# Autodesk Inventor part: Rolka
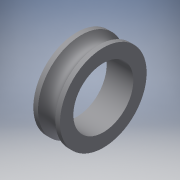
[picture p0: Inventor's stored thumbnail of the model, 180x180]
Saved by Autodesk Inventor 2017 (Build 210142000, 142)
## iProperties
Created: 2021-01
Part Number: Rolka
Material: Ogólny
Document SubType Name: Modeling
Designer: HP
Density: 1 g/cm^3
Appearance: Domyślna
Author: HP
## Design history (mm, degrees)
sketch "Szkic1"
  geometry: L1 (0, 0)-(47.708, 0); L2 (4.065, 4.5)-(0.065, 4.5); L3 (0.065, 4.5)-(0.065, 6.5); L4 (4.065, 4.5)-(4.065, 6.5); L5 (0.065, 6.5)-(0.765, 6.5); L6 (4.065, 6.5)-(3.365, 6.5); L7 (0.765, 6.5)-(2.065, 4.5); L8 (2.065, 4.5)-(3.365, 6.5)
  constraints: 12 end point, 3 horizontal, 1 midpoint, 1 vertical, 3 other
  dimensions: "d0" = 9 diameter of L2 L1; "d15" = 2 distance of L2.end L3.end; "d16" = 2 distance from line of L2 L4.end; "d17" = 4 distance of L4.end L3.end; "d18" = 0.7 distance of L5.end L3.end; "d19" = 0.7 distance of L4.end L6.end
revolve "Obrót1" sketch "Szkic1" stored, may be unused: angle "d14" = 90 deg
node "Bryła1"
